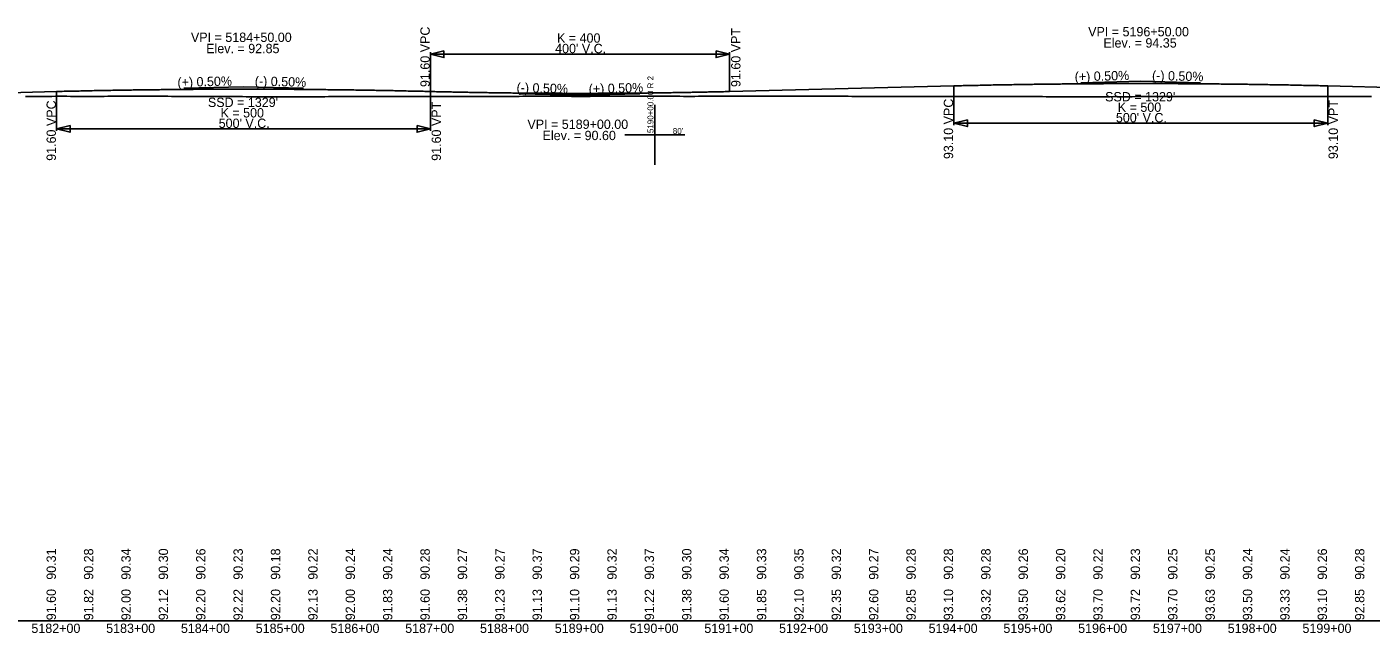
# Model space of a CAD drawing. Extents: x 2147288 to 2220488, y 740833 to 759333.
# Drawn here: x 2150541 to 2152339, y 742067 to 742878 of the extents above; entities that cross this region are included whole.
import ezdxf

# ---------------------------------------------------------------- set-up
doc = ezdxf.new("R2010")
doc.units = 0
for name, color, linetype in [('RD_DDB_GradeTX', 7, 'Continuous'), ('RD_DDB_Profile_EX', 7, 'Continuous'), ('RD_DDB_Profile_Lbl', 7, 'Continuous'), ('RD_DDB_Profile_PR', 7, 'Continuous'), ('RD_DDB_StaTX', 7, 'Continuous'), ('RD_DDB_StripGrade', 7, 'Continuous'), ('RD_DDB_VCLbl', 7, 'Continuous'), ('RD_GPK_Profile_Cell', 7, 'Continuous')]:
    doc.layers.add(name, color=color, linetype=linetype)

msp = doc.modelspace()

# ---------------------------------------------------------------- linework, layer by layer
at = {"layer": 'RD_DDB_GradeTX'}
for p, q in [((2150751.1, 742795.7), (2150831.1, 742797.7)), ((2150911.1, 742795.7), (2150831.1, 742797.7)), ((2151951.1, 742803.2), (2152031.1, 742805.2)), ((2152111.1, 742803.2), (2152031.1, 742805.2)), ((2151201.1, 742788.4), (2151281.1, 742786.4)), ((2151361.1, 742788.4), (2151281.1, 742786.4))]:
    msp.add_line(p, q, dxfattribs=at)
at = {"layer": 'RD_DDB_Profile_EX'}
for points in [[(2150539.6, 742784.7), (2150544.6, 742784.7), (2150549.6, 742784.7), (2150554.6, 742784.8), (2150559.6, 742784.8), (2150564.6, 742784.8), (2150569.6, 742784.9), (2150574.6, 742784.9), (2150579.6, 742785), (2150584.6, 742785), (2150589.6, 742785), (2150594.6, 742785), (2150599.6, 742784.9), (2150604.6, 742784.9), (2150609.6, 742784.9), (2150614.6, 742784.9), (2150619.6, 742784.8), (2150624.6, 742784.8), (2150629.6, 742784.8), (2150634.6, 742784.9), (2150639.6, 742784.9), (2150644.6, 742784.9), (2150649.6, 742785), (2150654.6, 742785), (2150659.6, 742785), (2150664.6, 742785.1), (2150669.6, 742785.1), (2150674.6, 742785.1), (2150679.6, 742785.1), (2150684.6, 742785.1), (2150689.6, 742785.1), (2150694.6, 742785.1), (2150699.6, 742785.1), (2150704.6, 742785.1), (2150709.6, 742785.1), (2150714.6, 742785.1), (2150719.6, 742785), (2150724.6, 742785), (2150729.6, 742785), (2150734.6, 742784.9), (2150739.6, 742784.9), (2150744.6, 742784.9), (2150749.6, 742784.8), (2150754.6, 742784.8), (2150759.6, 742784.8), (2150764.6, 742784.7), (2150769.6, 742784.7), (2150774.6, 742784.7), (2150779.6, 742784.7), (2150784.6, 742784.7), (2150789.6, 742784.7), (2150794.6, 742784.7), (2150799.6, 742784.7), (2150804.6, 742784.6), (2150809.6, 742784.6), (2150814.6, 742784.6), (2150819.6, 742784.6), (2150824.6, 742784.6), (2150829.6, 742784.6), (2150834.6, 742784.5), (2150839.6, 742784.5), (2150844.6, 742784.5), (2150849.6, 742784.5), (2150854.6, 742784.4), (2150859.6, 742784.4), (2150864.6, 742784.4), (2150869.6, 742784.3), (2150874.6, 742784.3), (2150879.6, 742784.3), (2150884.6, 742784.4), (2150889.6, 742784.4), (2150894.6, 742784.4), (2150899.6, 742784.4), (2150904.6, 742784.4), (2150909.6, 742784.4), (2150914.6, 742784.5), (2150919.6, 742784.5), (2150924.6, 742784.5), (2150929.6, 742784.5), (2150934.6, 742784.5), (2150939.6, 742784.5), (2150944.6, 742784.6), (2150949.6, 742784.6), (2150954.6, 742784.6), (2150959.6, 742784.6), (2150964.6, 742784.6), (2150969.6, 742784.6), (2150974.6, 742784.6), (2150979.6, 742784.6), (2150984.6, 742784.6), (2150989.6, 742784.6), (2150994.6, 742784.6), (2150999.6, 742784.6), (2151004.6, 742784.6), (2151009.6, 742784.6), (2151014.6, 742784.6), (2151019.6, 742784.6), (2151024.6, 742784.6), (2151029.6, 742784.6), (2151034.6, 742784.6)], [(2151034.6, 742784.6), (2151039.6, 742784.7), (2151044.6, 742784.7), (2151049.6, 742784.7), (2151054.6, 742784.7), (2151059.6, 742784.8), (2151064.6, 742784.8), (2151069.6, 742784.8), (2151074.6, 742784.8), (2151079.6, 742784.8), (2151084.6, 742784.8), (2151089.6, 742784.8), (2151094.6, 742784.8), (2151099.6, 742784.8), (2151104.6, 742784.8), (2151109.6, 742784.8), (2151114.6, 742784.8), (2151119.6, 742784.8), (2151124.6, 742784.8), (2151129.6, 742784.8), (2151134.6, 742784.8), (2151139.6, 742784.8), (2151144.6, 742784.8), (2151149.6, 742784.8), (2151154.6, 742784.7), (2151159.6, 742784.8), (2151164.6, 742784.8), (2151169.6, 742784.8), (2151174.6, 742784.8), (2151179.6, 742784.8), (2151184.6, 742784.8), (2151189.6, 742784.8), (2151194.6, 742784.8), (2151199.6, 742784.9), (2151204.6, 742785), (2151209.6, 742785), (2151214.6, 742785.1), (2151219.6, 742785.2), (2151224.6, 742785.2), (2151229.6, 742785.3), (2151234.6, 742785.3), (2151239.6, 742785.3), (2151244.6, 742785.2), (2151249.6, 742785.2), (2151254.6, 742785.1), (2151259.6, 742785), (2151264.6, 742785), (2151269.6, 742784.9), (2151274.6, 742784.9), (2151279.6, 742784.9), (2151284.6, 742784.9), (2151289.6, 742784.9), (2151294.6, 742784.9), (2151299.6, 742785), (2151304.6, 742785), (2151309.6, 742785), (2151314.6, 742785), (2151319.6, 742785), (2151324.6, 742785), (2151329.6, 742785), (2151334.6, 742785), (2151339.6, 742785), (2151344.6, 742785.1), (2151349.6, 742785.1), (2151354.6, 742785.1), (2151359.6, 742785.2), (2151364.6, 742785.2), (2151369.6, 742785.2), (2151374.6, 742785.3), (2151379.6, 742785.3), (2151384.6, 742785.3), (2151389.6, 742785.2), (2151394.6, 742785.2), (2151399.6, 742785.1), (2151404.6, 742785.1), (2151409.6, 742785), (2151414.6, 742785), (2151419.6, 742784.9), (2151424.6, 742784.9), (2151429.6, 742784.9), (2151434.6, 742784.9), (2151439.6, 742785), (2151444.6, 742785), (2151449.6, 742785), (2151454.6, 742785), (2151459.6, 742785), (2151464.6, 742785.1), (2151469.6, 742785.1), (2151474.6, 742785.1), (2151479.6, 742785.1), (2151484.6, 742785.2), (2151489.6, 742785.2), (2151494.6, 742785.2), (2151499.6, 742785.2), (2151504.6, 742785.3), (2151509.6, 742785.2), (2151514.6, 742785.2), (2151519.6, 742785.2), (2151524.6, 742785.1), (2151529.6, 742785.1), (2151534.6, 742785.1)], [(2151534.6, 742785.1), (2151539.6, 742785.1), (2151544.6, 742785), (2151549.6, 742785.1), (2151554.6, 742785.1), (2151559.6, 742785.1), (2151564.6, 742785.1), (2151569.6, 742785.1), (2151574.6, 742785.1), (2151579.6, 742785.2), (2151584.6, 742785.2), (2151589.6, 742785.2), (2151594.6, 742785.2), (2151599.6, 742785.2), (2151604.6, 742785.1), (2151609.6, 742785.1), (2151614.6, 742785.1), (2151619.6, 742785.1), (2151624.6, 742785.1), (2151629.6, 742785.1), (2151634.6, 742785), (2151639.6, 742785), (2151644.6, 742784.9), (2151649.6, 742784.9), (2151654.6, 742784.8), (2151659.6, 742784.8), (2151664.6, 742784.8), (2151669.6, 742784.8), (2151674.6, 742784.8), (2151679.6, 742784.8), (2151684.6, 742784.8), (2151689.6, 742784.8), (2151694.6, 742784.8), (2151699.6, 742784.8), (2151704.6, 742784.8), (2151709.6, 742784.8), (2151714.6, 742784.8), (2151719.6, 742784.8), (2151724.6, 742784.8), (2151729.6, 742784.8), (2151734.6, 742784.8), (2151739.6, 742784.8), (2151744.6, 742784.8), (2151749.6, 742784.8), (2151754.6, 742784.8), (2151759.6, 742784.8), (2151764.6, 742784.8), (2151769.6, 742784.8), (2151774.6, 742784.8), (2151779.6, 742784.8), (2151784.6, 742784.8), (2151789.6, 742784.8), (2151794.6, 742784.8), (2151799.6, 742784.8), (2151804.6, 742784.8), (2151809.6, 742784.8), (2151814.6, 742784.8), (2151819.6, 742784.8), (2151824.6, 742784.8), (2151829.6, 742784.8), (2151834.6, 742784.8), (2151839.6, 742784.8), (2151844.6, 742784.9), (2151849.6, 742784.9), (2151854.6, 742784.9), (2151859.6, 742784.9), (2151864.6, 742784.9), (2151869.6, 742784.8), (2151874.6, 742784.8), (2151879.6, 742784.7), (2151884.6, 742784.7), (2151889.6, 742784.7), (2151894.6, 742784.6), (2151899.6, 742784.6), (2151904.6, 742784.5), (2151909.6, 742784.5), (2151914.6, 742784.5), (2151919.6, 742784.5), (2151924.6, 742784.4), (2151929.6, 742784.4), (2151934.6, 742784.4), (2151939.6, 742784.4), (2151944.6, 742784.4), (2151949.6, 742784.4), (2151954.6, 742784.4), (2151959.6, 742784.5), (2151964.6, 742784.5), (2151969.6, 742784.5), (2151974.6, 742784.5), (2151979.6, 742784.5), (2151984.6, 742784.5), (2151989.6, 742784.5), (2151994.6, 742784.6), (2151999.6, 742784.5), (2152004.6, 742784.5), (2152009.6, 742784.5), (2152014.6, 742784.5), (2152019.6, 742784.5), (2152024.6, 742784.6), (2152029.6, 742784.6), (2152034.6, 742784.6)], [(2152034.6, 742784.6), (2152039.6, 742784.6), (2152044.6, 742784.7), (2152049.6, 742784.7), (2152054.6, 742784.7), (2152059.6, 742784.7), (2152064.6, 742784.7), (2152069.6, 742784.7), (2152074.6, 742784.7), (2152079.6, 742784.7), (2152084.6, 742784.7), (2152089.6, 742784.7), (2152094.6, 742784.6), (2152099.6, 742784.6), (2152104.6, 742784.6), (2152109.6, 742784.6), (2152114.6, 742784.6), (2152119.6, 742784.6), (2152124.6, 742784.7), (2152129.6, 742784.7), (2152134.6, 742784.7), (2152139.6, 742784.7), (2152144.6, 742784.7), (2152149.6, 742784.7), (2152154.6, 742784.7), (2152159.6, 742784.7), (2152164.6, 742784.6), (2152169.6, 742784.6), (2152174.6, 742784.6), (2152179.6, 742784.6), (2152184.6, 742784.6), (2152189.6, 742784.6), (2152194.6, 742784.6), (2152199.6, 742784.6), (2152204.6, 742784.6), (2152209.6, 742784.6), (2152214.6, 742784.6), (2152219.6, 742784.6), (2152224.6, 742784.6), (2152229.6, 742784.6), (2152234.6, 742784.6), (2152239.6, 742784.6), (2152244.6, 742784.6), (2152249.6, 742784.7), (2152254.6, 742784.7), (2152259.6, 742784.7), (2152264.6, 742784.7), (2152269.6, 742784.7), (2152274.6, 742784.7), (2152279.6, 742784.7), (2152284.6, 742784.7), (2152289.6, 742784.7), (2152294.6, 742784.7), (2152299.6, 742784.7), (2152304.6, 742784.7), (2152309.6, 742784.8), (2152314.6, 742784.8), (2152319.6, 742784.8), (2152324.6, 742784.8), (2152329.6, 742784.8), (2152334.6, 742784.9), (2152339.6, 742784.9)]]:
    msp.add_lwpolyline(points, dxfattribs=at)
at = {"layer": 'RD_DDB_Profile_PR'}
for p, q in [((2151481.1, 742791.4), (2151781.1, 742798.9)), ((2152281.1, 742798.9), (2152631.1, 742790.2)), ((2150431.1, 742787.7), (2150581.1, 742791.4))]:
    msp.add_line(p, q, dxfattribs=at)
for points in [[(2151781.1, 742798.9), (2151791.1, 742799.2), (2151801.1, 742799.4), (2151811.1, 742799.6), (2151821.1, 742799.8), (2151831.1, 742800.1), (2151841.1, 742800.2), (2151851.1, 742800.4), (2151861.1, 742800.6), (2151871.1, 742800.8), (2151881.1, 742800.9), (2151891.1, 742801.1), (2151901.1, 742801.2), (2151911.1, 742801.3), (2151921.1, 742801.4), (2151931.1, 742801.6), (2151941.1, 742801.6), (2151951.1, 742801.7), (2151961.1, 742801.8), (2151971.1, 742801.9), (2151981.1, 742801.9), (2151991.1, 742802), (2152001.1, 742802), (2152011.1, 742802), (2152021.1, 742802), (2152031.1, 742802.1), (2152041.1, 742802), (2152051.1, 742802), (2152061.1, 742802), (2152071.1, 742802), (2152081.1, 742801.9), (2152091.1, 742801.9), (2152101.1, 742801.8), (2152111.1, 742801.7), (2152121.1, 742801.6), (2152131.1, 742801.6), (2152141.1, 742801.4), (2152151.1, 742801.3), (2152161.1, 742801.2), (2152171.1, 742801.1), (2152181.1, 742800.9), (2152191.1, 742800.8), (2152201.1, 742800.6), (2152211.1, 742800.4), (2152221.1, 742800.2), (2152231.1, 742800.1), (2152241.1, 742799.8), (2152251.1, 742799.6), (2152261.1, 742799.4), (2152271.1, 742799.2), (2152281.1, 742798.9)], [(2150581.1, 742791.4), (2150591.1, 742791.7), (2150601.1, 742791.9), (2150611.1, 742792.1), (2150621.1, 742792.3), (2150631.1, 742792.6), (2150641.1, 742792.7), (2150651.1, 742792.9), (2150661.1, 742793.1), (2150671.1, 742793.3), (2150681.1, 742793.4), (2150691.1, 742793.6), (2150701.1, 742793.7), (2150711.1, 742793.8), (2150721.1, 742793.9), (2150731.1, 742794.1), (2150741.1, 742794.1), (2150751.1, 742794.2), (2150761.1, 742794.3), (2150771.1, 742794.4), (2150781.1, 742794.4), (2150791.1, 742794.5), (2150801.1, 742794.5), (2150811.1, 742794.5), (2150821.1, 742794.5), (2150831.1, 742794.6), (2150841.1, 742794.5), (2150851.1, 742794.5), (2150861.1, 742794.5), (2150871.1, 742794.5), (2150881.1, 742794.4), (2150891.1, 742794.4), (2150901.1, 742794.3), (2150911.1, 742794.2), (2150921.1, 742794.1), (2150931.1, 742794.1), (2150941.1, 742793.9), (2150951.1, 742793.8), (2150961.1, 742793.7), (2150971.1, 742793.6), (2150981.1, 742793.4), (2150991.1, 742793.3), (2151001.1, 742793.1), (2151011.1, 742792.9), (2151021.1, 742792.7), (2151031.1, 742792.6), (2151041.1, 742792.3), (2151051.1, 742792.1), (2151061.1, 742791.9), (2151071.1, 742791.7), (2151081.1, 742791.4)], [(2151081.1, 742791.4), (2151089.1, 742791.2), (2151097.1, 742791), (2151105.1, 742790.9), (2151113.1, 742790.7), (2151121.1, 742790.5), (2151129.1, 742790.4), (2151137.1, 742790.2), (2151145.1, 742790.1), (2151153.1, 742790), (2151161.1, 742789.8), (2151169.1, 742789.7), (2151177.1, 742789.6), (2151185.1, 742789.5), (2151193.1, 742789.4), (2151201.1, 742789.3), (2151209.1, 742789.3), (2151217.1, 742789.2), (2151225.1, 742789.1), (2151233.1, 742789.1), (2151241.1, 742789), (2151249.1, 742789), (2151257.1, 742789), (2151265.1, 742788.9), (2151273.1, 742788.9), (2151281.1, 742788.9), (2151289.1, 742788.9), (2151297.1, 742788.9), (2151305.1, 742789), (2151313.1, 742789), (2151321.1, 742789), (2151329.1, 742789.1), (2151337.1, 742789.1), (2151345.1, 742789.2), (2151353.1, 742789.3), (2151361.1, 742789.3), (2151369.1, 742789.4), (2151377.1, 742789.5), (2151385.1, 742789.6), (2151393.1, 742789.7), (2151401.1, 742789.8), (2151409.1, 742790), (2151417.1, 742790.1), (2151425.1, 742790.2), (2151433.1, 742790.4), (2151441.1, 742790.5), (2151449.1, 742790.7), (2151457.1, 742790.9), (2151465.1, 742791), (2151473.1, 742791.2), (2151481.1, 742791.4)]]:
    msp.add_spline(points, degree=3, dxfattribs=at)
at = {"layer": 'RD_DDB_VCLbl'}
for p, q in [((2151081.1, 742843.9), (2151081.1, 742791.4)), ((2151081.1, 742841.4), (2151481.1, 742841.4)), ((2151481.1, 742843.9), (2151481.1, 742791.4)), ((2151781.1, 742746.4), (2151781.1, 742798.9)), ((2152281.1, 742746.4), (2152281.1, 742798.9)), ((2150581.1, 742738.9), (2150581.1, 742791.4)), ((2151081.1, 742738.9), (2151081.1, 742791.4)), ((2150581.1, 742741.4), (2151081.1, 742741.4)), ((2151781.1, 742748.9), (2152281.1, 742748.9))]:
    msp.add_line(p, q, dxfattribs=at)
for points in [[(2151099.1, 742845.9), (2151081.1, 742841.4), (2151099.1, 742836.9)], [(2151463.1, 742845.9), (2151481.1, 742841.4), (2151463.1, 742836.9)], [(2150599.1, 742745.9), (2150581.1, 742741.4), (2150599.1, 742736.9)], [(2151063.1, 742745.9), (2151081.1, 742741.4), (2151063.1, 742736.9)], [(2151799.1, 742753.4), (2151781.1, 742748.9), (2151799.1, 742744.4)], [(2152263.1, 742753.4), (2152281.1, 742748.9), (2152263.1, 742744.4)]]:
    msp.add_lwpolyline(points, close=True, dxfattribs=at)
at = {"layer": 'RD_GPK_Profile_Cell'}
for p, q in [((2151381.1, 742773.4), (2151381.1, 742693.4)), ((2151421.1, 742733.4), (2151341.1, 742733.4)), ((2148888.3, 742083.4), (2165888.3, 742083.4))]:
    msp.add_line(p, q, dxfattribs=at)

# ---------------------------------------------------------------- texts
at = {"layer": 'RD_DDB_GradeTX'}
for s, rotation, p in [('(+) 0.50%', 1.4321, (2151942.8, 742805)), ('(-) 0.50%', 358.5679, (2152046, 742806.8)), ('(+) 0.50%', 1.4321, (2150742.8, 742797.5)), ('(-) 0.50%', 358.5679, (2150846, 742799.3)), ('(-) 0.50%', 358.5679, (2151196.1, 742790.6)), ('(+) 0.50%', 1.4321, (2151292.8, 742788.7))]:
    msp.add_text(s, height=12.5, rotation=rotation, dxfattribs=at).set_placement(p)
at = {"layer": 'RD_DDB_Profile_Lbl'}
for s, p in [('VPI = 5184+50.00', (2150760.7, 742857.7)), ('VPI = 5196+50.00', (2151960.7, 742865.2)), ('Elev. = 92.85', (2150781.1, 742842.7)), ('Elev. = 94.35', (2151981.1, 742850.2)), ('VPI = 5189+00.00', (2151210.7, 742741.4)), ('Elev. = 90.60', (2151231, 742726.4))]:
    msp.add_text(s, height=12.5, dxfattribs=at).set_placement(p)
at = {"layer": 'RD_DDB_StaTX'}
for s, p in [('5182+00', (2150547.3, 742067.2)), ('5183+00', (2150647.3, 742067.2)), ('5184+00', (2150747.3, 742067.2)), ('5185+00', (2150847.3, 742067.2)), ('5186+00', (2150947.3, 742067.2)), ('5187+00', (2151047.3, 742067.2)), ('5188+00', (2151147.3, 742067.2)), ('5189+00', (2151247.3, 742067.2)), ('5190+00', (2151347.3, 742067.2)), ('5191+00', (2151447.3, 742067.2)), ('5192+00', (2151547.3, 742067.2)), ('5193+00', (2151647.3, 742067.2)), ('5194+00', (2151747.3, 742067.2)), ('5195+00', (2151847.3, 742067.2)), ('5196+00', (2151947.3, 742067.2)), ('5197+00', (2152047.3, 742067.2)), ('5198+00', (2152147.3, 742067.2)), ('5199+00', (2152247.3, 742067.2))]:
    msp.add_text(s, height=12.5, dxfattribs=at).set_placement(p)
at = {"layer": 'RD_DDB_StripGrade'}
for s, p in [('91.60 VPC', (2151080.1, 742797.4)), ('91.60 VPT', (2151495.7, 742797.4)), ('91.60 VPC', (2150580.1, 742698.7)), ('91.60 VPT', (2151095.1, 742698.7)), ('93.10 VPC', (2151780.1, 742701)), ('93.10 VPT', (2152294.7, 742701)), ('90.31', (2150580.1, 742138.4)), ('90.28', (2150630.1, 742138.4)), ('90.34', (2150680.1, 742138.4)), ('90.30', (2150730.1, 742138.4)), ('90.26', (2150780.1, 742138.4)), ('90.23', (2150830.1, 742138.4)), ('90.18', (2150880.1, 742138.4)), ('90.22', (2150930.1, 742138.4)), ('90.24', (2150980.1, 742138.4)), ('90.24', (2151030.1, 742138.4)), ('90.28', (2151080.1, 742138.4)), ('90.27', (2151130.1, 742138.4)), ('90.27', (2151180.1, 742138.4)), ('90.37', (2151230.1, 742138.4)), ('90.29', (2151280.1, 742138.4)), ('90.32', (2151330.1, 742138.4)), ('90.37', (2151380.1, 742138.4)), ('90.30', (2151430.1, 742138.4)), ('90.34', (2151480.1, 742138.4)), ('90.33', (2151530.1, 742138.4)), ('90.35', (2151580.1, 742138.4)), ('90.32', (2151630.1, 742138.4)), ('90.27', (2151680.1, 742138.4)), ('90.28', (2151730.1, 742138.4)), ('90.28', (2151780.1, 742138.4)), ('90.28', (2151830.1, 742138.4)), ('90.26', (2151880.1, 742138.4)), ('90.20', (2151930.1, 742138.4)), ('90.22', (2151980.1, 742138.4)), ('90.23', (2152030.1, 742138.4)), ('90.25', (2152080.1, 742138.4)), ('90.25', (2152130.1, 742138.4)), ('90.24', (2152180.1, 742138.4)), ('90.24', (2152230.1, 742138.4)), ('90.26', (2152280.1, 742138.4)), ('90.28', (2152330.1, 742138.4)), ('91.60', (2150580.1, 742084.2)), ('91.82', (2150630.1, 742084.2)), ('92.00', (2150680.1, 742084.2)), ('92.12', (2150730.1, 742084.2)), ('92.20', (2150780.1, 742084.2)), ('92.22', (2150830.1, 742084.2)), ('92.20', (2150880.1, 742084.2)), ('92.13', (2150930.1, 742084.2)), ('92.00', (2150980.1, 742084.2)), ('91.83', (2151030.1, 742084.2)), ('91.60', (2151080.1, 742084.2)), ('91.38', (2151130.1, 742084.2)), ('91.23', (2151180.1, 742084.2)), ('91.13', (2151230.1, 742084.2)), ('91.10', (2151280.1, 742084.2)), ('91.13', (2151330.1, 742084.2)), ('91.22', (2151380.1, 742084.2)), ('91.38', (2151430.1, 742084.2)), ('91.60', (2151480.1, 742084.2)), ('91.85', (2151530.1, 742084.2)), ('92.10', (2151580.1, 742084.2)), ('92.35', (2151630.1, 742084.2)), ('92.60', (2151680.1, 742084.2)), ('92.85', (2151730.1, 742084.2)), ('93.10', (2151780.1, 742084.2)), ('93.32', (2151830.1, 742084.2)), ('93.50', (2151880.1, 742084.2)), ('93.62', (2151930.1, 742084.2)), ('93.70', (2151980.1, 742084.2)), ('93.72', (2152030.1, 742084.2)), ('93.70', (2152080.1, 742084.2)), ('93.63', (2152130.1, 742084.2)), ('93.50', (2152180.1, 742084.2)), ('93.33', (2152230.1, 742084.2)), ('93.10', (2152280.1, 742084.2)), ('92.85', (2152330.1, 742084.2))]:
    msp.add_text(s, height=12.5, rotation=90, dxfattribs=at).set_placement(p)
at = {"layer": 'RD_DDB_VCLbl'}
for s, p in [('K = 400', (2151250.3, 742856.7)), ("400' V.C.", (2151247.8, 742842.7)), ("SSD = 1329'", (2150783.4, 742770.7)), ("SSD = 1329'", (2151983.4, 742778.2)), ('K = 500', (2150800.3, 742756.7)), ("500' V.C.", (2151997.8, 742750.2)), ('K = 500', (2152000.3, 742764.2)), ("500' V.C.", (2150797.8, 742742.7))]:
    msp.add_text(s, height=12.5, dxfattribs=at).set_placement(p)
at = {"layer": 'RD_GPK_Profile_Cell'}
msp.add_text('5190+00.00 R 2', height=8, rotation=90, dxfattribs=at).set_placement((2151379.3, 742735.8))
msp.add_text("80'", height=8, dxfattribs=at).set_placement((2151405.2, 742734.6))

doc.saveas('drawing.dxf')
